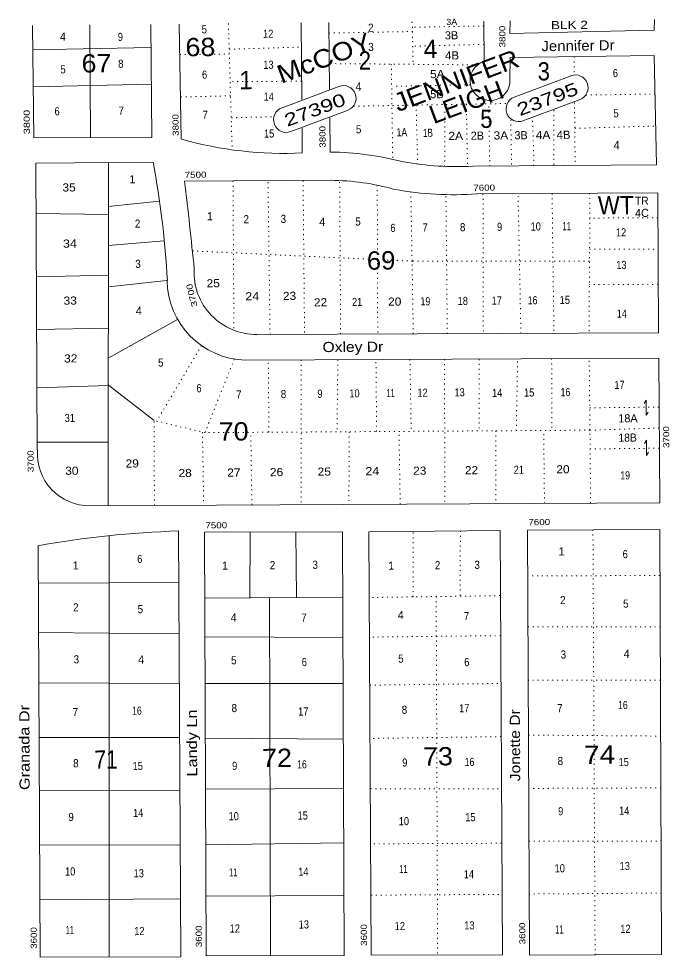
# Model space of a CAD drawing. Extents: x 2356373 to 2371954, y 6966197 to 6989612.
# Drawn here: x 2363089 to 2364359, y 6983007 to 6984854 of the extents above; entities that cross this region are included whole.
import ezdxf

# ---------------------------------------------------------------- set-up
doc = ezdxf.new("R2010")
doc.units = 0
doc.header["$LTSCALE"] = 6.4
doc.linetypes.add('DOTTED', pattern=[1.5, 0.3, -1.2])
for name, color, linetype in [('10', 7, 'Continuous'), ('18', 7, 'Continuous'), ('22', 7, 'Continuous'), ('24', 7, 'Continuous')]:
    doc.layers.add(name, color=color, linetype=linetype)
for name, color, linetype, lineweight in [('12', 7, 'Continuous', 13), ('13', 7, 'Continuous', 13), ('15', 7, 'Continuous', 13), ('16', 7, 'DOTTED', 13), ('17', 7, 'Continuous', 13), ('19', 7, 'Continuous', 13), ('6', 7, 'DOTTED', 13), ('9', 7, 'DOTTED', 13)]:
    doc.layers.add(name, color=color, linetype=linetype, lineweight=lineweight)

msp = doc.modelspace()

# ---------------------------------------------------------------- linework, layer by layer
at = {"layer": '13'}
for points in [[(2364319.569, 6984096.929), (2364323.504, 6984103.466), (2364323.8, 6984073.477), (2364327.733, 6984080.013)], [(2364320.345, 6984018.059), (2364324.279, 6984024.595), (2364324.574, 6983994.606), (2364328.508, 6984001.143)]]:
    msp.add_lwpolyline(points, dxfattribs=at)
at = {"layer": '15'}
for p, q in [((2363645.871, 6984695.251), (2363644.39, 6984846.095)), ((2363699.369, 6984846.636), (2363700.656, 6984715.683)), ((2364004.259, 6984849.631), (2364005.04, 6984770.158)), ((2363404.477, 6984843.739), (2363408.704, 6984616.941)), ((2364055.951, 6984777.757), (2364055.378, 6984734.263)), ((2363701.211, 6984659.103), (2363701.872, 6984591.827)), ((2363646.905, 6984589.988), (2363646.426, 6984638.771)), ((2363703.419, 6984536.258), (2363415.511, 6984534.63))]:
    msp.add_line(p, q, dxfattribs=at)
for points in [[(2364340.137, 6984852.929), (2364339.344, 6984831.827), (2364055.484, 6984825.34), (2364056.24, 6984850.141)], [(2363348.496, 6984843.189), (2363350.686, 6984620.371), (2363118.755, 6984619.591), (2363115.582, 6984840.901)], [(2364055.951, 6984777.757), (2364339.835, 6984781.845), (2364343.944, 6984566.942), (2363983.07, 6984564.098)], [(2363352.16, 6984571.997), (2363122.241, 6984570.039), (2363124.788, 6984005.315)], [(2363557.439, 6984232.705), (2364348.2, 6984235.573), (2364346.486, 6984511.782), (2363990.603, 6984509.587)], [(2363228.84, 6983895.465), (2364350.484, 6983901.285), (2364348.685, 6984186.191), (2363534.946, 6984181.798)], [(2363403.279, 6983845.993), (2363407.518, 6983007.358), (2363130.6, 6983006.539), (2363126.64, 6983816.783)]]:
    msp.add_lwpolyline(points, dxfattribs=at)
for points in [[(2364090.08, 6983847.64), (2364351, 6983848.704), (2364354.219, 6983012.059), (2364094.305, 6983010.406)], [(2363454.293, 6983843.195), (2363726.213, 6983843.967), (2363729.406, 6983010.121), (2363457.488, 6983009.15)], [(2363778.198, 6983844.177), (2364036.107, 6983846.412), (2364041.306, 6983011.585), (2363782.385, 6983010.74)]]:
    msp.add_lwpolyline(points, close=True, dxfattribs=at)
for centre, radius, start, end in [((2364016.405, 6984732.581), 39.367, 107.29276, 2.39276), ((2363612.465, 6985348.148), 758.941, 254.46276, 272.62276), ((2363693.863, 6983982.312), 609.588, 75.50776, 89.27576), ((2361662.778, 6984249.685), 1720.758, 2.96676, 10.79576), ((2363950.351, 6985147.021), 583.856, 259.74276, 273.18276), ((2352772.611, 6983286.797), 10715.623, 5.75476, 6.68776), ((2363699.065, 6984063.341), 472.941, 74.17276, 89.54676), ((2363944.354, 6985146.862), 639.029, 259.59276, 274.19276), ((2363556.235, 6984355.26), 122.511, 177.20276, 270.61276), ((2363540.377, 6984341.308), 159.6, 180.89276, 268.02276), ((2363227.834, 6983997.929), 102.468, 175.85276, 270.64276), ((2363470.609, 6981876.78), 1970.279, 91.96476, 100.06476)]:
    msp.add_arc(centre, radius, start, end, dxfattribs=at)
at = {"layer": '16'}
for p in [(2364212.531, 6984510.966), (2364346.972, 6984462.401)]:
    msp.add_line(p, (2364213.012, 6984461.884), dxfattribs=at)
at = {"layer": '17'}
for p, q in [((2364063.713, 6984699.955), (2364176.268, 6984742.149)), ((2363607.04, 6984678.974), (2363718.598, 6984721.157)), ((2364081.168, 6984653.238), (2364193.724, 6984695.333)), ((2363624.495, 6984632.258), (2363737.052, 6984674.351))]:
    msp.add_line(p, q, dxfattribs=at)
for centre, start, end in [((2364184.497, 6984718.736), 290.56276, 110.56276), ((2363727.825, 6984697.755), 290.56276, 110.56276), ((2364072.94, 6984676.651), 110.56276, 290.56276), ((2363615.269, 6984655.56), 110.56276, 290.56276)]:
    msp.add_arc(centre, 24.992, start, end, dxfattribs=at)
at = {"layer": '6'}
for p, q in [((2363863.31, 6984848.246), (2363865.131, 6984764.586)), ((2363501.44, 6984844.691), (2363508.881, 6984596.23)), ((2363864.496, 6984829.163), (2363699.57, 6984826.143)), ((2364004.351, 6984840.134), (2363863.415, 6984837.549)), ((2363502.937, 6984794.218), (2363644.857, 6984798.513)), ((2364004.707, 6984803.947), (2363864.781, 6984800.172)), ((2363406.063, 6984783.97), (2363503.034, 6984784.423)), ((2364181.899, 6984779.594), (2364182.228, 6984746.106)), ((2363992.108, 6984763.534), (2363700.163, 6984765.965)), ((2363822.139, 6984764.963), (2363824.98, 6984577.44)), ((2363645.517, 6984731.338), (2363504.562, 6984730.452)), ((2363977.497, 6984724.401), (2363823.568, 6984721.289)), ((2363505.836, 6984702.672), (2363407.886, 6984700.21)), ((2364341.579, 6984706.082), (2364205.635, 6984704.047)), ((2363747.973, 6984682.058), (2364048.841, 6984687.411)), ((2363870.92, 6984684.263), (2363874.059, 6984568.226)), ((2363927.09, 6984563.547), (2363927.894, 6984685.223)), ((2363969.876, 6984685.935), (2363972.078, 6984563.59)), ((2364016.058, 6984564.322), (2364013.857, 6984686.767)), ((2364182.786, 6984689.426), (2364184, 6984565.672)), ((2364141.946, 6984674.229), (2364142.013, 6984565.36)), ((2363507.26, 6984659.297), (2363588.22, 6984661.292)), ((2364057.153, 6984655.401), (2364059.044, 6984564.644)), ((2364103.028, 6984564.976), (2364100.11, 6984658.524)), ((2364183.285, 6984638.545), (2364342.198, 6984643.106)), ((2363510.479, 6984535.163), (2363512.37, 6984240.961)), ((2363583.43, 6984232.86), (2363579.458, 6984535.54)), ((2363648.436, 6984535.918), (2363651.41, 6984233.128)), ((2363722.389, 6984233.325), (2363720.418, 6984535.824)), ((2363794.488, 6984526.656), (2363795.367, 6984233.542)), ((2363865.346, 6984233.828), (2363860.601, 6984513.308)), ((2363932.326, 6984234.087), (2363929.636, 6984507.988)), ((2364002.601, 6984509.604), (2364003.305, 6984234.284)), ((2364077.282, 6984234.612), (2364071.578, 6984510.082)), ((2364138.555, 6984510.44), (2364142.261, 6984234.85)), ((2364213.012, 6984461.884), (2364211.241, 6984235.029)), ((2364212.618, 6984400.297), (2364347.579, 6984400.622)), ((2364347.261, 6984331.239), (2364212.299, 6984330.912)), ((2363448.682, 6984210.943), (2363360.172, 6984061.713)), ((2363512.928, 6984184.08), (2363455.367, 6984039.353)), ((2363581.324, 6984040.192), (2363579.93, 6984182.039)), ((2363644.911, 6984182.378), (2363644.708, 6983897.651)), ((2363716.887, 6984182.785), (2363715.28, 6984041.006)), ((2363793.255, 6984041.571), (2363791.864, 6984183.122)), ((2363858.842, 6984183.478), (2363861.232, 6984041.94)), ((2363926.821, 6984183.847), (2363927.618, 6983899.13)), ((2363994.798, 6984184.215), (2363995.187, 6984042.856)), ((2364068.164, 6984043.273), (2364070.774, 6984184.661)), ((2364137.753, 6984185.019), (2364138.14, 6984043.762)), ((2364214.527, 6983900.549), (2364211.728, 6984185.445)), ((2363355.8, 6983896.113), (2363355.16, 6984063.061)), ((2363450.356, 6984040.504), (2363452.769, 6983896.667)), ((2363547.739, 6983897.099), (2363545.337, 6984039.937)), ((2363739.273, 6984041.143), (2363738.679, 6983898.074)), ((2363839.647, 6983898.667), (2363837.239, 6984041.805)), ((2364028.176, 6984043.08), (2364027.587, 6983899.613)), ((2364123.555, 6983900.156), (2364122.147, 6984043.604)), ((2363865.434, 6983716.068), (2363865.167, 6983844.932)), ((2363958.134, 6983845.745), (2363957.395, 6983717.372)), ((2364219.041, 6983848.207), (2364223.262, 6983011.273)), ((2364350.89, 6983758.127), (2364090.968, 6983757.273)), ((2364036.364, 6983718.448), (2363779.468, 6983714.824)), ((2363910.415, 6983716.711), (2363913.346, 6983011.127)), ((2364090.951, 6983657.199), (2364351.886, 6983656.764)), ((2364037.138, 6983639.676), (2363779.234, 6983636.843)), ((2363780.164, 6983542.177), (2364037.063, 6983545.501)), ((2364351.913, 6983552.193), (2364091.986, 6983551.838)), ((2364092.047, 6983443.868), (2364351.996, 6983441.923)), ((2364038.091, 6983440.839), (2363780.194, 6983437.405)), ((2363781.166, 6983338.441), (2364039.103, 6983337.874)), ((2364352.998, 6983339.959), (2364093.078, 6983338.905)), ((2364039.153, 6983230.905), (2363781.232, 6983229.871)), ((2364093.099, 6983234.933), (2364353.026, 6983235.387)), ((2363782.226, 6983128.707), (2364040.141, 6983130.341)), ((2364354.033, 6983132.824), (2364094.121, 6983130.972))]:
    msp.add_line(p, q, dxfattribs=at)
at = {"layer": '6', "linetype": 'Continuous'}
for p, q in [((2363228.54, 6984842.01), (2363229.722, 6984619.981)), ((2363116.05, 6984793.319), (2363348.946, 6984797.505)), ((2363349.653, 6984725.331), (2363117.763, 6984720.555)), ((2363265.191, 6984571.343), (2363264.829, 6983895.62)), ((2363365.913, 6984495.053), (2363265.042, 6984484.565)), ((2363123.218, 6984470.575), (2363265.194, 6984469.17)), ((2363264.799, 6984407.582), (2363374.679, 6984416.76)), ((2363265.37, 6984349.405), (2363123.438, 6984346.41)), ((2363380.441, 6984339.037), (2363265.598, 6984326.212)), ((2363264.977, 6984185.844), (2363401.189, 6984262.362)), ((2363124.459, 6984242.448), (2363265.397, 6984244.832)), ((2363124.584, 6984127.88), (2363265.502, 6984132.462)), ((2363355.16, 6984063.061), (2363265.499, 6984132.663)), ((2363265.598, 6984020.894), (2363125.637, 6984020.719)), ((2363266.41, 6983836.451), (2363266.559, 6983006.974)), ((2363543.537, 6983714.206), (2363544.267, 6983843.479)), ((2363634.241, 6983843.663), (2363635.509, 6983714.711)), ((2363404.28, 6983744.23), (2363127.364, 6983743.209)), ((2363726.479, 6983715.203), (2363454.565, 6983713.732)), ((2363582.525, 6983714.389), (2363584.449, 6983009.596)), ((2363127.318, 6983646.135), (2363404.27, 6983643.456)), ((2363727.254, 6983636.232), (2363455.317, 6983637.26)), ((2363405.231, 6983545.493), (2363128.292, 6983546.972)), ((2363455.218, 6983545.584), (2363727.144, 6983545.655)), ((2363128.35, 6983439.201), (2363405.275, 6983439.321)), ((2363727.221, 6983436.085), (2363456.274, 6983438.022)), ((2363405.296, 6983335.349), (2363129.385, 6983333.839)), ((2363456.263, 6983337.45), (2363728.177, 6983338.719)), ((2363129.428, 6983227.668), (2363406.356, 6983227.489)), ((2363728.226, 6983232.05), (2363457.339, 6983227.89)), ((2363457.333, 6983126.716), (2363729.245, 6983128.287)), ((2363406.394, 6983121.718), (2363130.488, 6983119.706))]:
    msp.add_line(p, q, dxfattribs=at)
at = {"layer": '6'}
for points in [[(2364211.849, 6984376.695), (2363863.941, 6984376.879), (2363430.856, 6984397.217)], [(2364213.117, 6984044.198), (2363455.367, 6984039.353), (2363355.16, 6984063.061)]]:
    msp.add_lwpolyline(points, dxfattribs=at)
at = {"layer": '9'}
for p, q in [((2364212.683, 6984088.282), (2364348.633, 6984089.617)), ((2364213.117, 6984044.198), (2364349.037, 6984048.43)), ((2364349.428, 6984008.746), (2364213.478, 6984007.41))]:
    msp.add_line(p, q, dxfattribs=at)

# ---------------------------------------------------------------- texts
at = {"layer": '10', "width": 0.95}
msp.add_text('TR', height=15.99, rotation=0.563, dxfattribs=at).set_placement((2364301.734, 6984487.849))
at = {"layer": '10'}
msp.add_text('4C', height=15.99, rotation=0.563, dxfattribs=at).set_placement((2364301.97, 6984463.858))
at = {"layer": '12'}
for s, height, width, p in [('3A', 12, 1.1, (2363930.353, 6984842.006)), ('5', 15.99, 0.9, (2363448.645, 6984825.378)), ('12', 15.99, 0.85, (2363569.699, 6984816.669)), ('2', 15.99, 0.9, (2363776.525, 6984828.599)), ('9', 15.99, 0.85, (2363283.834, 6984810.563)), ('3', 15.99, 0.9, (2363776.9, 6984790.612)), ('8', 15.99, 0.9, (2363284.353, 6984757.781)), ('4B', 15.99, 1.05, (2363928.023, 6984774.001)), ('5', 15.99, 0.9, (2363170.492, 6984746.665)), ('13', 15.99, 0.85, (2363570.297, 6984755.592)), ('6', 15.99, 0.85, (2364258.275, 6984739.255)), ('6', 15.99, 0.85, (2363449.522, 6984736.209)), ('5A', 15.99, 1.1, (2363898.391, 6984737.32)), ('14', 15.99, 0.85, (2363570.914, 6984692.913)), ('6', 15.99, 0.85, (2363159.308, 6984664.078)), ('7', 15.99, 0.9, (2363285.261, 6984665.315)), ('7', 15.99, 0.9, (2363450.299, 6984657.038)), ('5', 15.99, 0.9, (2364259.053, 6984660.083)), ('5', 15.99, 0.9, (2363752.497, 6984628.615)), ('15', 15.99, 0.85, (2363571.628, 6984620.24)), ('1A', 15.99, 0.8, (2363832.532, 6984622.803)), ('1B', 15.99, 0.75, (2363884.53, 6984621.714)), ('2A', 15.99, 1.1, (2363934.577, 6984615.608)), ('3A', 15.99, 1.1, (2364023.544, 6984616.482)), ('4A', 15.99, 1.1, (2364106.515, 6984617.298)), ('4B', 15.99, 1.05, (2364147.499, 6984617.7)), ('35', 15.99, 1.1, (2363174.777, 6984514.069)), ('2', 15.99, 0.9, (2363317.438, 6984442.891)), ('2', 15.99, 0.9, (2363531.295, 6984451.588)), ('3', 15.99, 0.9, (2363604.269, 6984452.306)), ('5', 15.99, 0.9, (2363751.279, 6984447.152)), ('6', 15.99, 0.85, (2363820.386, 6984434.534)), ('7', 15.99, 0.9, (2363883.364, 6984435.154)), ('8', 15.99, 0.9, (2363957.337, 6984435.879)), ('9', 15.99, 0.85, (2364030.311, 6984436.595)), ('10', 15.99, 0.85, (2364096.286, 6984437.244)), ('11', 15.99, 0.55, (2364159.263, 6984437.862)), ('12', 15.99, 0.85, (2364264.354, 6984425.698)), ('34', 15.99, 1.15, (2363175.863, 6984403.51)), ('3', 15.99, 0.9, (2363318.217, 6984363.621)), ('13', 15.99, 0.85, (2364264.986, 6984361.421)), ('25', 15.99, 1.1, (2363458.555, 6984325.408)), ('24', 15.99, 1.15, (2363534.786, 6984299.764)), ('23', 15.99, 1.1, (2363608.759, 6984300.49)), ('33', 15.99, 1.1, (2363176.965, 6984291.252)), ('22', 15.99, 1.1, (2363669.866, 6984287.894)), ('21', 15.99, 0.85, (2363744.839, 6984288.63)), ('20', 15.99, 1.1, (2363815.814, 6984289.329)), ('19', 15.99, 0.8, (2363879.79, 6984289.956)), ('18', 15.99, 0.85, (2363952.764, 6984290.673)), ('17', 15.99, 0.85, (2364019.74, 6984291.331)), ('16', 15.99, 0.8, (2364090.714, 6984292.027)), ('15', 15.99, 0.85, (2364153.691, 6984292.646)), ('14', 15.99, 0.85, (2364265.926, 6984265.657)), ('32', 15.99, 1.1, (2363178.084, 6984177.392)), ('5', 15.99, 0.9, (2363363.114, 6984169.313)), ('6', 15.99, 0.85, (2363438.589, 6984118.867)), ('12', 15.99, 0.85, (2363873.561, 6984109.943)), ('13', 15.99, 0.85, (2363946.534, 6984110.66)), ('14', 15.99, 0.85, (2364020.523, 6984109.787)), ('15', 15.99, 0.85, (2364083.5, 6984110.406)), ('16', 15.99, 0.8, (2364155.474, 6984111.113)), ('17', 15.99, 0.85, (2364261.306, 6984125.349)), ('7', 15.99, 0.9, (2363516.691, 6984106.437)), ('8', 15.99, 0.9, (2363604.658, 6984107.302)), ('9', 15.99, 0.85, (2363676.634, 6984108.009)), ('10', 15.99, 0.85, (2363739.609, 6984108.628)), ('11', 15.99, 0.55, (2363812.583, 6984109.345)), ('31', 15.99, 0.85, (2363179.235, 6984060.235)), ('18B', 15.99, 0.95, (2364269.324, 6984021.455)), ('29', 15.99, 1.1, (2363299.082, 6983970.636)), ('30', 15.99, 1.1, (2363180.256, 6983956.272)), ('28', 15.99, 1.1, (2363403.238, 6983951.865)), ('27', 15.99, 1.1, (2363499.205, 6983952.806)), ('26', 15.99, 1.1, (2363583.173, 6983953.631)), ('25', 15.99, 1.1, (2363677.141, 6983954.556)), ('24', 15.99, 1.15, (2363771.106, 6983955.478)), ('23', 15.99, 1.1, (2363865.072, 6983956.4)), ('22', 15.99, 1.1, (2363967.035, 6983957.402)), ('21', 15.99, 0.85, (2364062.999, 6983958.346)), ('20', 15.99, 1.1, (2364146.969, 6983959.17)), ('19', 15.99, 0.8, (2364273.054, 6983947.212)), ('6', 15.99, 0.85, (2363321.924, 6983782.711)), ('6', 15.99, 0.85, (2364277.576, 6983792.097)), ('2', 15.99, 0.9, (2363582.974, 6983770.479)), ('3', 15.99, 0.9, (2363666.943, 6983771.304)), ('2', 15.99, 0.9, (2363907.889, 6983770.371)), ('3', 15.99, 0.9, (2363985.86, 6983771.137)), ('2', 15.99, 0.9, (2363195.894, 6983687.399)), ('2', 15.99, 0.9, (2364154.496, 6983701.812)), ('5', 15.99, 0.9, (2364278.532, 6983694.732)), ('5', 15.99, 0.9, (2363322.895, 6983683.747)), ('7', 15.99, 0.9, (2363644.973, 6983667.115)), ('7', 15.99, 0.9, (2363964.856, 6983670.258)), ('3', 15.99, 0.9, (2364155.549, 6983594.551)), ('3', 15.99, 0.9, (2363196.898, 6983585.135)), ('5', 15.99, 0.9, (2363506.834, 6983583.181)), ('6', 15.99, 0.85, (2363645.832, 6983579.648)), ('5', 15.99, 0.9, (2363835.715, 6983586.411)), ('6', 15.99, 0.85, (2363965.748, 6983579.49)), ('16', 15.99, 0.8, (2363311.862, 6983483.892)), ('8', 15.99, 0.9, (2363507.759, 6983489.114)), ('17', 15.99, 0.85, (2363638.791, 6983482.204)), ('8', 15.99, 0.9, (2363842.7, 6983485.806)), ('17', 15.99, 0.85, (2363955.644, 6983488.617)), ('7', 15.99, 0.9, (2364148.591, 6983488.811)), ('16', 15.99, 0.8, (2364268.496, 6983494.988)), ('7', 15.99, 0.9, (2363194.919, 6983481.144)), ('8', 15.99, 0.9, (2363195.908, 6983380.479)), ('15', 15.99, 0.85, (2363312.932, 6983375.032)), ('9', 15.99, 0.85, (2363508.877, 6983375.257)), ('16', 15.99, 0.8, (2363636.814, 6983378.213)), ('9', 15.99, 0.85, (2363843.722, 6983381.844)), ('16', 15.99, 0.8, (2363966.677, 6983383.052)), ('8', 15.99, 0.9, (2364149.611, 6983384.85)), ('15', 15.99, 0.85, (2364269.6, 6983382.729)), ('14', 15.99, 0.85, (2363313.839, 6983282.565)), ('9', 15.99, 0.85, (2364150.583, 6983285.885)), ('14', 15.99, 0.85, (2364270.54, 6983287.063)), ('9', 15.99, 0.85, (2363186.951, 6983274.72)), ('10', 15.99, 0.85, (2363501.851, 6983276.214)), ('15', 15.99, 0.85, (2363637.803, 6983277.549)), ('10', 15.99, 0.85, (2363836.859, 6983266.307)), ('15', 15.99, 0.85, (2363967.747, 6983274.192)), ('10', 15.99, 0.85, (2363180.007, 6983167.381)), ('14', 15.99, 0.85, (2363638.887, 6983166.989)), ('11', 15.99, 0.55, (2363837.783, 6983172.242)), ('10', 15.99, 0.85, (2364143.689, 6983173.546)), ('13', 15.99, 0.85, (2364271.609, 6983178.102)), ('13', 15.99, 0.85, (2363315.006, 6983163.808)), ('11', 15.99, 0.55, (2363502.937, 6983165.654)), ('14', 15.99, 0.85, (2363964.852, 6983161.894)), ('13', 15.99, 0.85, (2363639.91, 6983063.027)), ('12', 15.99, 0.85, (2363828.889, 6983059.885)), ('13', 15.99, 0.85, (2363965.84, 6983061.23)), ('11', 15.99, 0.55, (2363181.141, 6983051.923)), ('12', 15.99, 0.85, (2363316.125, 6983049.949)), ('12', 15.99, 0.85, (2363504.023, 6983055.094)), ('11', 15.99, 0.55, (2364144.873, 6983053.091)), ('12', 15.99, 0.85, (2364272.825, 6983054.347))]:
    msp.add_text(s, height=height, rotation=0.563, dxfattribs=dict(at, width=width)).set_placement(p)
for s, p in [('3B', (2363927.634, 6984813.586)), ('4', (2363169.861, 6984811.043)), ('4', (2363751.671, 6984712.785)), ('5B', (2363898.779, 6984697.734)), ('2B', (2363978.56, 6984616.039)), ('3B', (2364064.53, 6984616.884)), ('4', (2364259.67, 6984597.308)), ('1', (2363306.584, 6984530.162)), ('1', (2363459.257, 6984457.48)), ('4', (2363680.307, 6984446.456)), ('4', (2363319.125, 6984271.253)), ('18A', (2364268.952, 6984059.442)), ('1', (2364151.557, 6983797.458)), ('1', (2363195.082, 6983769.968)), ('1', (2363489.007, 6983769.556)), ('1', (2363815.922, 6983769.468)), ('4', (2363506.008, 6983667.35)), ('4', (2363834.871, 6983672.279)), ('4', (2364279.505, 6983595.769)), ('4', (2363323.868, 6983584.683))]:
    msp.add_text(s, height=15.99, rotation=0.563, dxfattribs=at).set_placement(p)
at = {"layer": '17', "width": 1.35}
for s, p in [('23795', (2364075.081, 6984662.276)), ('27390', (2363617.408, 6984641.285))]:
    msp.add_text(s, height=24.99, rotation=20.563, dxfattribs=at).set_placement(p)
at = {"layer": '18'}
for s, width, p in [('McCOY', 1.15, (2363605.58, 6984726.047)), ('JENNIFER', 1.1, (2363835.066, 6984670.216)), ('LEIGH', 1.05, (2363905.281, 6984646.512))]:
    msp.add_text(s, height=35.99, rotation=20.563, dxfattribs=dict(at, width=width)).set_placement(p)
at = {"layer": '19'}
for s, rotation, width, p in [('Jennifer Dr', 0.808, 1.1, (2364117.81, 6984790.362)), ('Oxley Dr', 0.313, 1.15, (2363686.746, 6984197.985)), ('Granada Dr', 90.29, 1.2, (2363110.371, 6983335.75)), ('Landy Ln', 90.239, 1.2, (2363440.022, 6983362.283)), ('Jonette Dr', 90.325, 1.15, (2364075.943, 6983353.035))]:
    msp.add_text(s, height=19.99, rotation=rotation, dxfattribs=dict(at, width=width)).set_placement(p)
at = {"layer": '22'}
for s, height, width, p in [('BLK 2', 15.99, 1.25, (2364136.38, 6984833.733)), ('68', 35.99, 1.1, (2363417.095, 6984780.38)), ('2', 35.99, 0.9, (2363758.263, 6984754.038)), ('67', 35.99, 1.1, (2363212.465, 6984748.377)), ('3', 35.99, 0.9, (2364110.379, 6984732.704)), ('5', 35.99, 0.9, (2363997.328, 6984639.219)), ('WT', 35.99, 0.95, (2364228.938, 6984468.939)), ('69', 35.99, 1.05, (2363774.128, 6984360.199)), ('70', 35.99, 1.1, (2363482.514, 6984023.525)), ('74', 35.99, 1.15, (2364201.577, 6983386.96)), ('71', 35.99, 0.85, (2363237.928, 6983377.493)), ('72', 35.99, 1.1, (2363567.808, 6983380.734)), ('73', 35.99, 1.1, (2363884.691, 6983383.847))]:
    msp.add_text(s, height=height, rotation=0.563, dxfattribs=dict(at, width=width)).set_placement(p)
for s, p in [('4', (2363886.006, 6984776.788)), ('1', (2363522.706, 6984715.435))]:
    msp.add_text(s, height=35.99, rotation=0.563, dxfattribs=at).set_placement(p)
at = {"layer": '24'}
for s, rotation, width, p in [('3800', 90.563, 1.2, (2364046.756, 6984797.862)), (' 3800', 90.563, 1.35, (2363110.745, 6984620.912)), ('3800', 90.563, 1.2, (2363403.638, 6984623.788)), ('3800', 90.563, 1.2, (2363692.79, 6984600.436)), ('7500', 0.563, 1.2, (2363415.45, 6984540.828)), ('7600', 0.563, 1.2, (2363983.549, 6984515.415)), ('3700', 104.263, 1.3, (2363440.922, 6984288.645)), ('3700', 90.563, 1.2, (2364369.417, 6984009.342)), ('3700', 90.563, 1.2, (2363118.22, 6983961.662)), ('7600', 0.563, 1.2, (2364091.988, 6983857.057)), ('7500', 0.563, 1.2, (2363456.218, 6983850.813)), ('3600', 90.563, 1.2, (2364086.094, 6983032.018)), ('3600', 90.563, 1.2, (2363124.439, 6983023.073)), ('3600', 90.563, 1.2, (2363449.321, 6983026.264)), ('3600', 90.563, 1.2, (2363774.208, 6983028.955))]:
    msp.add_text(s, height=12, rotation=rotation, dxfattribs=dict(at, width=width)).set_placement(p)

doc.saveas('drawing.dxf')
